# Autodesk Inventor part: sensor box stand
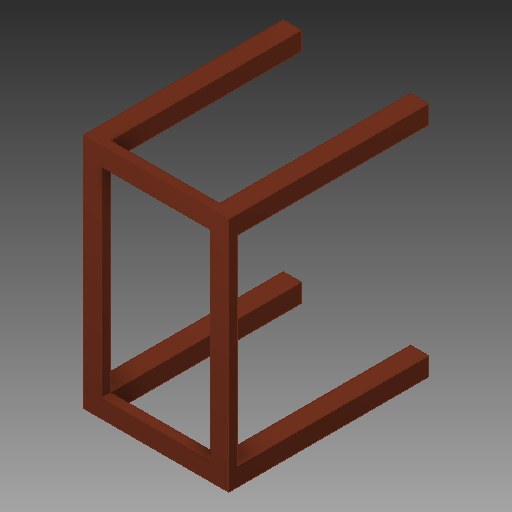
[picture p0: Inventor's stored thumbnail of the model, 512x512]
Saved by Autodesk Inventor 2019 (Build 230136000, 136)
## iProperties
Created: 2021-07
Part Number: sensor box stand
Material: Copper, Alloy
Document SubType Name: Modeling
Designer: Avinash
Density: 8.92 g/cm^3
Appearance: Copper - Satin
Author: Avinash
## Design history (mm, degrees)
sketch "Sketch1"
  geometry: L1 (0, 0)-(-80, 0); L2 (-80, 0)-(-80, 130); L3 (-80, 130)-(0, 130); L4 (0, 130)-(0, 0); L5 (-10, 10)-(-70, 10); L6 (-70, 10)-(-70, 120); L7 (-70, 120)-(-10, 120); L8 (-10, 120)-(-10, 10)
  constraints: 16 end point, 2 parallel, 1 horizontal, 1 perpendicular
  dimensions: "d1" = 130 distance of L1.end L2.end
extrude "Extrusion3" new body sketch "Sketch1" distance "d6" = 5; taper "d7" = 0 deg
sketch "Sketch4"
  geometry: L1 (10, 10)-(70, 10) reference; L2 (0, 0)-(10, 0); L3 (10, 0)-(10, 10); L4 (10, 10)-(0, 10); L5 (0, 10)-(0, 0); L6 (80, 0)-(0, 0) reference; L7 (80, 0)-(70, 0); L8 (70, 0)-(70, 10); L9 (70, 10)-(80, 10); L10 (80, 10)-(80, 0); L11 (0, 130)-(80, 130) reference; L12 (70, 120)-(10, 120) reference; L13 (0, 130)-(10, 130); L14 (10, 130)-(10, 120); L15 (10, 120)-(0, 120); L16 (0, 120)-(0, 130); L17 (80, 130)-(70, 130); L18 (70, 130)-(70, 120); L19 (70, 120)-(80, 120); L20 (80, 120)-(80, 130)
  constraints: 32 end point, 8 parallel, 4 horizontal, 4 perpendicular, 2 point on line
  dimensions: "d17" = 10 distance of L8.end L9.end; "d18" = 10 distance of L12.start L19.end
extrude "Extrusion5" join sketch "Sketch4" distance "d19" = 105; taper "d20" = 0 deg
body "Solid2"
